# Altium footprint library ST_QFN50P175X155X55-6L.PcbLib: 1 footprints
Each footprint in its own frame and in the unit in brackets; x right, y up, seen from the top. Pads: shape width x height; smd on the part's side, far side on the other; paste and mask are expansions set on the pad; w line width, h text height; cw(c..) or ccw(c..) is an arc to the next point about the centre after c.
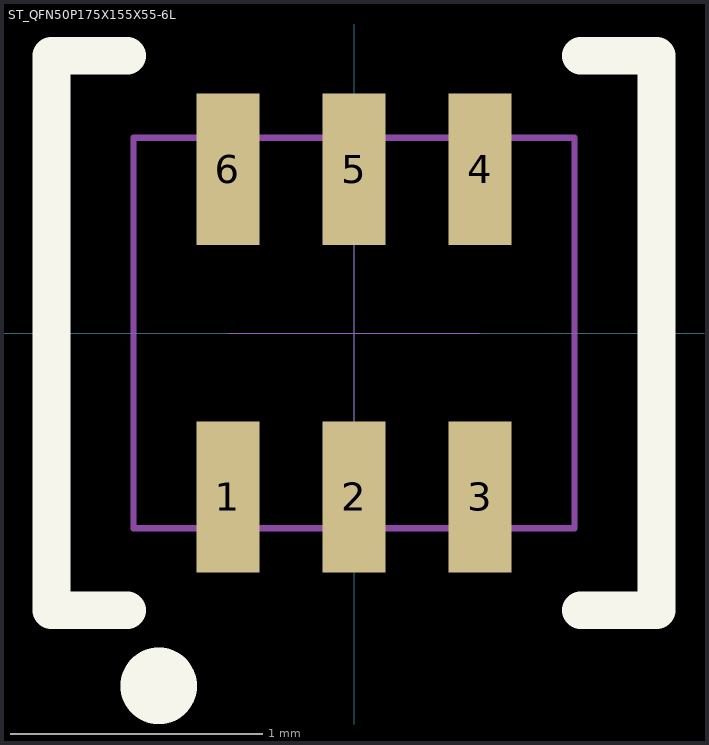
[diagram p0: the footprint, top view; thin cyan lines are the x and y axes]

## ST_QFN50P175X155X55-6L [mm] "ST_QFN50P175X155X55-6L"
pads (6):
  rect 0.25x0.6 smd paste-20 mask+0.05: 1(-0.5,-0.65) 2(0,-0.65) 3(0.5,-0.65) 4(0.5,0.65) 5(0,0.65) 6(-0.5,0.65)
Top Overlay:
  circle w0.254: c-0.775,-1.4 r0.025
  lines w0.15: -0.9,-1.1 -1.2,-1.1 -1.2,1.1 -0.9,1.1 ; 0.9,-1.1 1.2,-1.1 1.2,1.1 0.9,1.1
Top Paste:
  rectangle: -0.619,0.365 -0.382,0.935
  rectangle: -0.119,0.365 0.119,0.935
  rectangle: 0.382,0.365 0.619,0.935
  rectangle: -0.619,-0.935 -0.382,-0.365
  rectangle: -0.119,-0.935 0.119,-0.365
  rectangle: 0.382,-0.935 0.619,-0.365
Mechanical 5:
  text "1" at -0.51,-1.15 h0.05
  text "6" at -0.54,1.085 h0.05
  text "2" at -0.01,-1.15 h0.05
  text "5" at -0.04,1.085 h0.05
  text "3" at 0.49,-1.15 h0.05
  text "4" at 0.46,1.085 h0.05
Mechanical 6:
  lines w0.025: -0.875,-0.775 0.875,-0.775 0.875,0.775 -0.875,0.775 -0.875,-0.775
Mechanical 7:
  lines w0.025: -0.875,-0.775 -0.875,0.775 0.875,0.775 0.875,-0.775 -0.875,-0.775
Mechanical 15:
  lines w0.001: -0.5,0 0.5,0 ; 0,-0.5 0,0.5
3D body: height 0.55, standoff 0, extent -0.875,-0.775 0.875,0.775
3D body "DFN_170x150x55_6L_sym.STEP": height 0.56, standoff 0.01, extent -0.85,-0.75 0.85,0.75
